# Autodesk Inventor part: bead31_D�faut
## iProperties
Created: 2011-01
Part Number: bead31_D�faut
Document SubType Name: Modeling
Designer: eric
Density: 1 g/cm^3
Mass: 0.0737663 g
Surface Area: 2.05598 cm^2
Volume: 0.0737663 cm^3
Author: eric
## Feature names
1. Base1
